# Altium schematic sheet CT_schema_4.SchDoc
size 259 x 245 mm
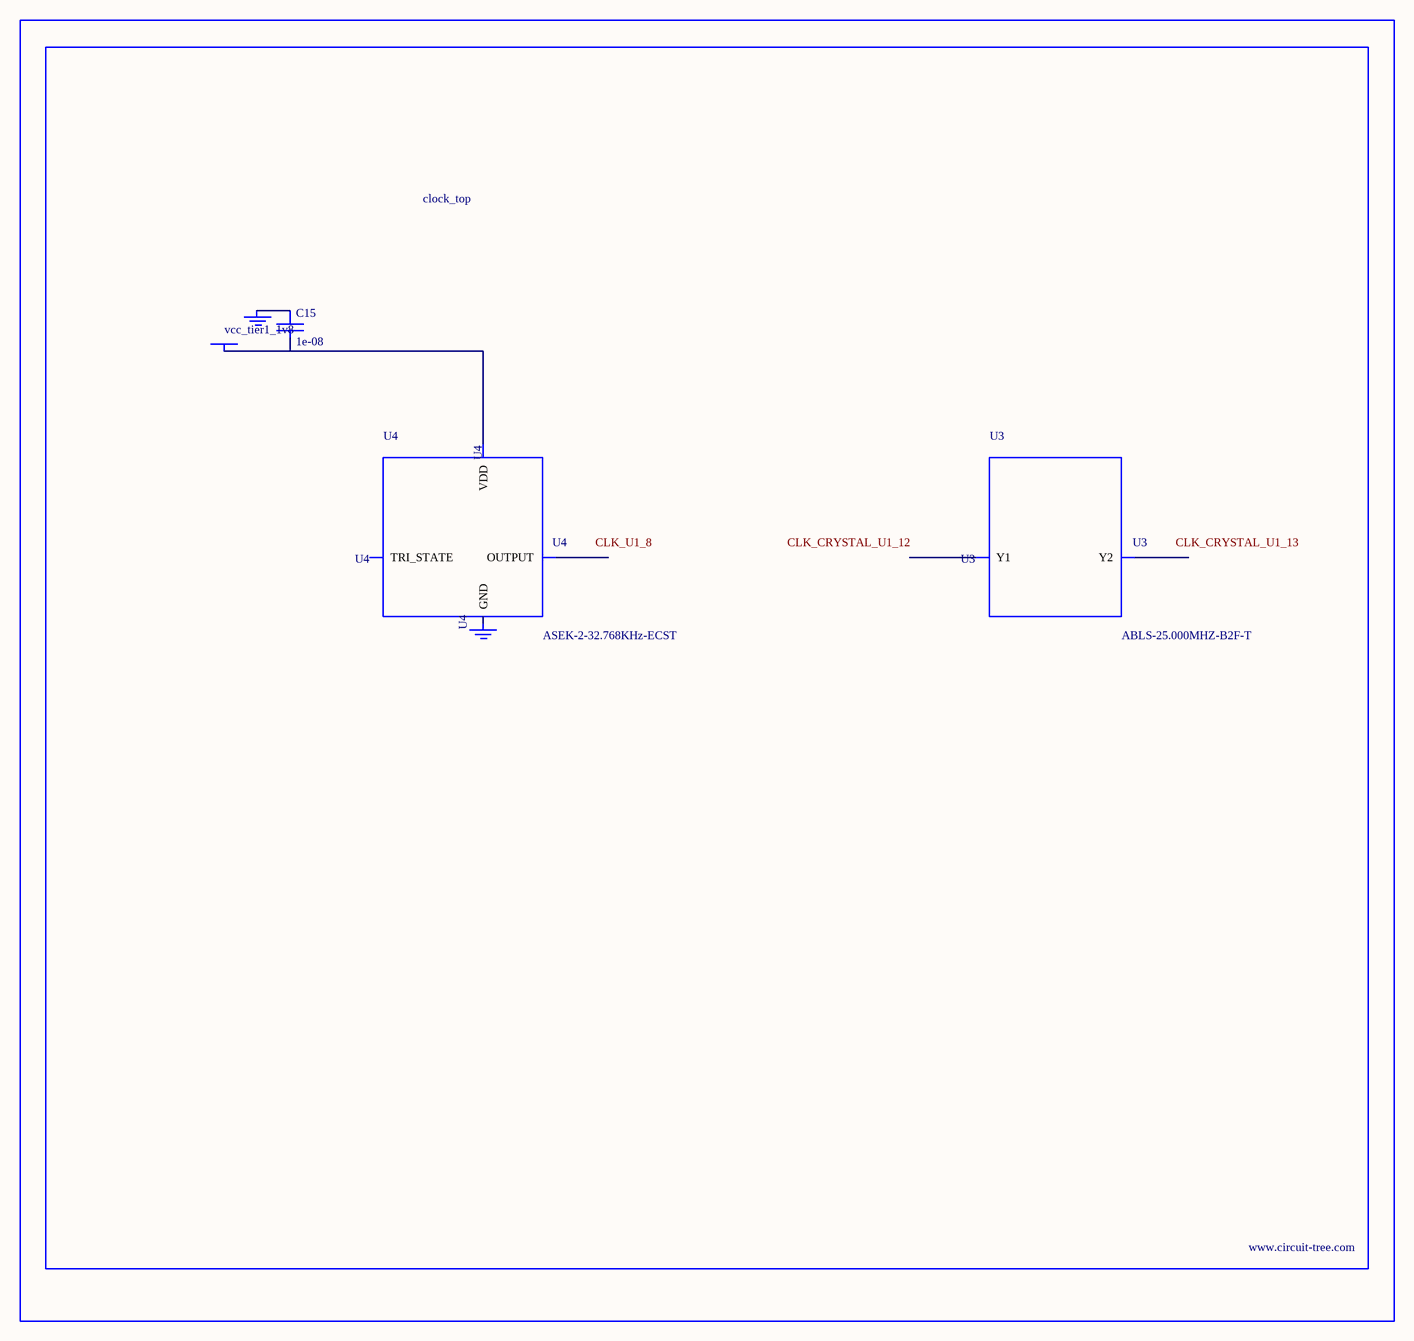
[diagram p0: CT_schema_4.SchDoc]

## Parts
BORDER3  (no value)
C15  1e-08  [C0402]
GND_INSTANCE_3_0  (no value)
GND_INSTANCE_3_1  (no value)
POWER_INSTANCE_3_0  vcc_tier1_1v8
U3  ABLS-25.000MHZ-B2F-T  [ABLS-25.000MHZ-B2F-T]
U4  ASEK-2-32.768KHz-ECST  [ASEK]

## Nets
NetC15_1: C15.1 GND_INSTANCE_3_0.0(GND)
NetC15_2: C15.2 POWER_INSTANCE_3_0.0(PWR) U4.4(VDD)

Not connected (* = marked no-connect by the designer): GND_INSTANCE_3_1 0(GND); U3 1(Y1) 2(Y2); U4 1(TRI_STATE) 2(GND) 3(OUTPUT)

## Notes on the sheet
- Labels drawn without touching a wire or pin: CLK_CRYSTAL_U1_12, CLK_CRYSTAL_U1_13, CLK_U1_8

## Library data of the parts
BORDER3 = BORDER_PAGE3
C15 = C0402C103K3RAC
GND_INSTANCE_3_0 GND_INSTANCE_3_1 = GND
POWER_INSTANCE_3_0 = PWR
